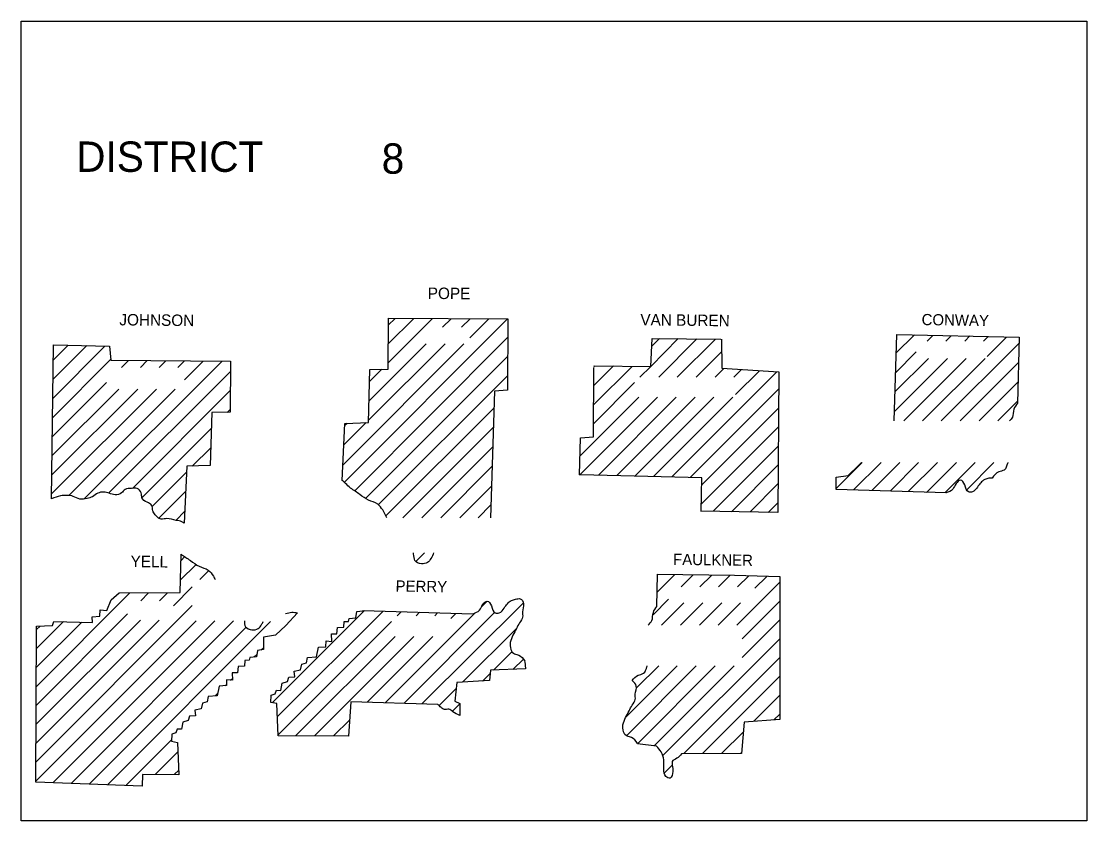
# Model space of a CAD drawing. Extents: x 23481 to 28196, y 1325020 to 1327623.
# Drawn here: x 27790.8 to 28190.8, y 1325699 to 1325999 of the extents above; entities that cross this region are included whole.
import ezdxf

# ---------------------------------------------------------------- set-up
doc = ezdxf.new("R2010")
doc.units = 0
doc.layers.add('S_ELECTRIC_UTILITIES_ANNOT', color=7, linetype='Continuous')

msp = doc.modelspace()

# ---------------------------------------------------------------- linework, layer by layer
at = {"layer": 'S_ELECTRIC_UTILITIES_ANNOT'}
msp.add_lwpolyline([(27790.76, 1325699.02), (27790.76, 1325999.02), (28190.76, 1325999.02), (28190.76, 1325699.02)], close=True, dxfattribs=at)
for points in [[(27911.26, 1325826.72), (27912.26, 1325848.12), (27921.06, 1325848.42), (27921.66, 1325868.32), (27928.56, 1325868.42), (27928.66, 1325887.62)], [(27912.06, 1325826.02), (27973.36, 1325887.32), (27973.36, 1325887.42)], [(27928.56, 1325870.82), (27945.16, 1325887.52)], [(27928.56, 1325877.92), (27938.16, 1325887.52)], [(27928.56, 1325885.02), (27931.16, 1325887.52)], [(27928.66, 1325887.62), (27973.46, 1325887.32)], [(27948.96, 1325884.22), (27952.16, 1325887.42)], [(27956.06, 1325884.22), (27959.26, 1325887.42)], [(27959.16, 1325880.22), (27966.26, 1325887.32)], [(27973.46, 1325887.32), (27973.26, 1325860.62), (27968.46, 1325860.22), (27966.96, 1325812.72)], [(27915.96, 1325822.82), (27973.36, 1325880.32)], [(28005.76, 1325869.72), (28027.06, 1325869.52), (28027.56, 1325880.02), (28053.36, 1325879.72)], [(28118.46, 1325849.02), (28119.46, 1325881.52)], [(28119.16, 1325874.42), (28126.06, 1325881.32)], [(28119.46, 1325881.52), (28165.36, 1325880.42), (28164.76, 1325855.72)], [(28130.86, 1325879.02), (28132.96, 1325881.12)], [(28137.86, 1325879.02), (28139.86, 1325881.02)], [(28144.96, 1325879.02), (28146.86, 1325880.92)], [(28152.06, 1325879.02), (28153.66, 1325880.62)], [(28153.36, 1325873.22), (28160.66, 1325880.52)], [(27802.16, 1325819.82), (27802.86, 1325877.62)], [(27802.56, 1325857.52), (27822.16, 1325877.12)], [(27802.66, 1325864.62), (27815.36, 1325877.32)], [(27802.76, 1325871.82), (27808.36, 1325877.42)], [(27802.86, 1325877.62), (27823.86, 1325877.12), (27824.36, 1325871.82)], [(27911.56, 1325832.62), (27956.96, 1325878.02)], [(27921.16, 1325849.32), (27949.86, 1325878.02)], [(27921.36, 1325856.62), (27942.76, 1325878.02)], [(28022.96, 1325865.42), (28027.06, 1325869.52), (28037.36, 1325879.92)], [(28027.36, 1325876.92), (28030.36, 1325879.92)], [(28030.06, 1325865.42), (28044.36, 1325879.82)], [(28037.06, 1325865.42), (28051.36, 1325879.72)], [(28053.66, 1325879.72), (28053.76, 1325868.82), (28075.16, 1325867.42), (28074.86, 1325814.72)], [(28136.16, 1325849.02), (28165.26, 1325878.12)], [(27802.56, 1325850.32), (27824.26, 1325872.12)], [(27920.16, 1325820.02), (27973.36, 1325873.22)], [(28044.16, 1325865.42), (28053.66, 1325874.92)], [(28118.56, 1325852.62), (28138.46, 1325872.52)], [(28118.76, 1325859.92), (28131.36, 1325872.52)], [(28118.96, 1325867.12), (28126.76, 1325874.92)], [(28122.06, 1325849.02), (28145.56, 1325872.52)], [(28129.16, 1325849.02), (28152.66, 1325872.52)], [(27814.36, 1325819.82), (27866.16, 1325871.52)], [(27824.36, 1325871.82), (27869.26, 1325871.52)], [(27828.36, 1325869.12), (27830.96, 1325871.72)], [(27835.46, 1325869.12), (27838.06, 1325871.72)], [(27842.56, 1325869.12), (27845.06, 1325871.62)], [(27849.56, 1325869.12), (27852.06, 1325871.62)], [(27869.26, 1325871.52), (27869.16, 1325852.32), (27862.26, 1325852.22), (27861.66, 1325832.32), (27852.86, 1325832.02), (27851.86, 1325810.62)], [(27852.06, 1325864.52), (27859.06, 1325871.52)], [(27921.46, 1325863.82), (27926.06, 1325868.42)], [(28000.36, 1325828.82), (28000.76, 1325842.72), (28005.56, 1325843.12), (28005.76, 1325869.12)], [(28005.66, 1325855.22), (28020.06, 1325869.52)], [(28005.76, 1325862.32), (28013.06, 1325869.72)], [(28005.76, 1325869.42), (28006.06, 1325869.72)], [(28051.26, 1325865.42), (28054.56, 1325868.72)], [(28058.26, 1325865.42), (28061.16, 1325868.32)], [(28143.26, 1325849.02), (28165.06, 1325870.82)], [(27823.66, 1325822.02), (27869.16, 1325867.52)], [(27924.86, 1325817.72), (27973.26, 1325866.02)], [(28035.06, 1325828.02), (28074.46, 1325867.42)], [(28058.86, 1325858.92), (28067.86, 1325867.82)], [(27802.26, 1325821.82), (27841.46, 1325861.02)], [(27802.36, 1325828.92), (27834.46, 1325861.02)], [(27802.36, 1325836.02), (27827.36, 1325861.02)], [(27802.46, 1325843.22), (27822.76, 1325863.52)], [(27808.56, 1325821.02), (27848.56, 1325861.02)], [(27832.46, 1325823.72), (27869.16, 1325860.42)], [(28005.66, 1325848.12), (28020.96, 1325863.42)], [(28041.96, 1325827.92), (28075.06, 1325861.02)], [(28150.36, 1325849.02), (28164.96, 1325863.62)], [(28000.46, 1325828.72), (28000.46, 1325828.82), (28029.56, 1325857.92)], [(28000.66, 1325836.02), (28022.56, 1325857.92)], [(28007.46, 1325828.72), (28036.66, 1325857.92)], [(28014.36, 1325828.52), (28043.76, 1325857.92)], [(28021.26, 1325828.42), (28050.76, 1325857.92)], [(28028.16, 1325828.22), (28057.96, 1325857.92)], [(28157.46, 1325849.02), (28164.76, 1325856.42)], [(27868.06, 1325852.22), (27869.16, 1325853.32)], [(27927.56, 1325813.32), (27968.26, 1325853.92)], [(28046.26, 1325825.12), (28075.06, 1325853.82)], [(27911.86, 1325840.02), (27920.26, 1325848.42)], [(27912.26, 1325847.42), (27913.06, 1325848.22)], [(27836.16, 1325820.32), (27862.06, 1325846.22)], [(27934.06, 1325812.72), (27968.06, 1325846.72)], [(28046.06, 1325817.82), (28075.06, 1325846.82)], [(27854.96, 1325832.02), (27861.86, 1325838.92)], [(27941.16, 1325812.72), (27967.76, 1325839.32)], [(28050.46, 1325815.12), (28074.96, 1325839.62)], [(27948.26, 1325812.72), (27967.56, 1325832.02)], [(28057.36, 1325814.92), (28074.96, 1325832.62)], [(28096.66, 1325823.32), (28096.66, 1325827.92), (28101.16, 1325828.62), (28105.06, 1325832.32), (28106.16, 1325833.42)], [(28096.66, 1325823.72), (28106.46, 1325833.42)], [(28103.26, 1325823.22), (28113.56, 1325833.42)], [(28110.06, 1325822.92), (28120.56, 1325833.42)], [(28116.96, 1325822.72), (28127.66, 1325833.42)], [(28123.76, 1325822.52), (28134.76, 1325833.42)], [(28130.66, 1325822.22), (28141.86, 1325833.42)], [(28137.46, 1325822.02), (28148.86, 1325833.42)], [(28145.76, 1325823.22), (28155.96, 1325833.42)], [(27839.96, 1325817.02), (27852.66, 1325829.72)], [(28045.96, 1325815.12), (28046.26, 1325827.72), (28000.56, 1325828.82)], [(27955.36, 1325812.72), (27967.36, 1325824.72)], [(28064.36, 1325814.92), (28074.86, 1325825.42)], [(27842.56, 1325812.62), (27852.46, 1325822.52)], [(28137.96, 1325822.02), (28096.76, 1325823.32)], [(27962.26, 1325812.72), (27967.06, 1325817.52)], [(28071.16, 1325814.72), (28074.86, 1325818.32)], [(27848.86, 1325811.82), (27852.06, 1325815.02)], [(28074.86, 1325814.72), (28045.76, 1325815.12)], [(27796.26, 1325713.52), (27796.46, 1325772.02), (27802.46, 1325772.22), (27802.96, 1325773.82), (27817.46, 1325773.42), (27817.36, 1325775.52), (27820.26, 1325775.82), (27820.36, 1325778.12), (27822.86, 1325777.92), (27824.56, 1325781.92), (27827.56, 1325784.52), (27850.36, 1325784.62), (27850.76, 1325799.02)], [(27850.76, 1325796.72), (27852.06, 1325798.02)], [(27938.86, 1325796.32), (27942.16, 1325799.52)], [(27850.46, 1325789.32), (27856.36, 1325795.22)], [(27857.76, 1325789.52), (27861.06, 1325792.82)], [(28029.36, 1325779.42), (28029.66, 1325791.52)], [(28029.46, 1325791.52), (28058.56, 1325791.12)], [(28029.46, 1325784.82), (28035.96, 1325791.32)], [(28038.46, 1325786.72), (28042.96, 1325791.32)], [(28058.56, 1325791.12), (28075.56, 1325790.62), (28075.56, 1325737.02), (28062.16, 1325736.02), (28061.16, 1325724.22), (28038.66, 1325724.12)], [(28045.46, 1325786.72), (28049.96, 1325791.22)], [(28052.56, 1325786.72), (28056.96, 1325791.12)], [(28059.46, 1325772.42), (28075.56, 1325788.52)], [(28059.66, 1325786.72), (28063.86, 1325790.92)], [(28066.16, 1325786.22), (28070.66, 1325790.72)], [(27796.46, 1325749.42), (27831.46, 1325784.52)], [(27835.66, 1325781.52), (27838.56, 1325784.52)], [(27842.66, 1325781.52), (27845.66, 1325784.52)], [(27847.86, 1325779.62), (27854.96, 1325786.72)], [(27941.16, 1325742.82), (27979.26, 1325780.82)], [(27963.56, 1325779.32), (27965.66, 1325781.42)], [(28027.96, 1325776.22), (28033.76, 1325782.12)], [(28031.16, 1325772.42), (28039.56, 1325780.82)], [(28038.26, 1325772.42), (28046.66, 1325780.82)], [(28045.36, 1325772.42), (28053.76, 1325780.82)], [(28052.36, 1325772.42), (28060.76, 1325780.82)], [(28061.36, 1325767.22), (28075.56, 1325781.42)], [(27796.36, 1325721.12), (27854.96, 1325779.72)], [(27796.46, 1325742.32), (27830.66, 1325776.62)], [(27894.46, 1325777.02), (27890.06, 1325772.32), (27886.16, 1325768.62), (27881.66, 1325767.92), (27881.66, 1325763.22), (27879.46, 1325762.92), (27879.06, 1325760.52), (27876.56, 1325760.32), (27876.36, 1325759.22), (27874.66, 1325759.12), (27874.56, 1325757.02), (27872.16, 1325756.92), (27871.96, 1325754.52), (27869.96, 1325754.52), (27870.06, 1325751.72), (27867.86, 1325751.92), (27867.76, 1325749.72), (27865.06, 1325749.52), (27864.26, 1325745.92), (27860.86, 1325745.62), (27860.56, 1325743.62), (27858.76, 1325743.12), (27858.26, 1325741.02), (27855.96, 1325740.52), (27856.16, 1325738.42), (27853.86, 1325738.22), (27853.46, 1325736.62), (27851.36, 1325736.02), (27850.86, 1325733.32), (27849.26, 1325733.42), (27848.76, 1325732.02), (27847.26, 1325731.52), (27847.16, 1325728.82), (27849.46, 1325728.42), (27849.86, 1325716.22)], [(27887.16, 1325730.82), (27886.76, 1325743.02), (27884.46, 1325743.42), (27884.56, 1325746.12), (27886.06, 1325746.62), (27886.56, 1325748.02), (27888.16, 1325747.92), (27888.66, 1325750.62), (27890.76, 1325751.22), (27891.16, 1325752.82), (27893.46, 1325753.02), (27893.26, 1325755.12), (27895.56, 1325755.62), (27896.06, 1325757.72), (27897.86, 1325758.22), (27898.16, 1325760.22), (27901.56, 1325760.52), (27902.36, 1325764.12), (27905.06, 1325764.32), (27905.16, 1325766.52), (27907.36, 1325766.32), (27907.26, 1325769.12), (27909.26, 1325769.12), (27909.46, 1325771.52), (27911.86, 1325771.62), (27911.96, 1325773.72), (27913.66, 1325773.82), (27913.86, 1325774.92), (27916.36, 1325775.12), (27916.76, 1325777.52), (27918.96, 1325777.82), (27918.96, 1325777.92)], [(27885.06, 1325743.32), (27919.66, 1325777.92)], [(27886.96, 1325738.12), (27926.56, 1325777.62)], [(27919.06, 1325777.92), (27960.26, 1325776.62)], [(27927.56, 1325743.32), (27960.96, 1325776.72)], [(27931.86, 1325775.92), (27933.36, 1325777.42)], [(27934.36, 1325743.02), (27968.46, 1325777.12)], [(27938.96, 1325775.92), (27940.26, 1325777.22)], [(27945.96, 1325775.92), (27947.06, 1325777.02)], [(27952.06, 1325774.92), (27953.86, 1325776.72)], [(27796.36, 1325728.12), (27842.56, 1325774.32)], [(27796.36, 1325714.02), (27856.36, 1325774.02)], [(27796.46, 1325735.32), (27835.46, 1325774.32)], [(27796.46, 1325763.62), (27806.66, 1325773.72)], [(27796.46, 1325756.62), (27813.46, 1325773.52)], [(27796.46, 1325770.72), (27797.86, 1325772.02)], [(27802.76, 1325713.32), (27863.46, 1325774.02)], [(27809.46, 1325713.02), (27870.46, 1325774.02)], [(27823.16, 1325712.52), (27884.36, 1325773.72)], [(27887.16, 1325731.22), (27929.76, 1325773.82)], [(28061.36, 1325760.22), (28075.56, 1325774.42)], [(27816.26, 1325712.72), (27875.16, 1325771.62)], [(27893.76, 1325730.82), (27931.16, 1325768.12)], [(27900.86, 1325730.82), (27938.16, 1325768.12)], [(27920.66, 1325743.52), (27945.26, 1325768.12)], [(27956.46, 1325751.02), (27976.76, 1325771.32)], [(27880.76, 1325763.12), (27881.66, 1325763.92), (27881.86, 1325764.12)], [(28031.56, 1325723.32), (28075.56, 1325767.32)], [(27878.06, 1325760.42), (27879.26, 1325761.52)], [(27968.06, 1325755.52), (27974.96, 1325762.42)], [(28039.56, 1325724.22), (28075.56, 1325760.22)], [(27979.76, 1325758.72), (27980.06, 1325756.02), (27966.96, 1325755.52), (27966.56, 1325751.62), (27954.26, 1325750.92), (27953.56, 1325743.92), (27955.36, 1325743.02), (27955.36, 1325738.52)], [(27975.36, 1325755.72), (27979.26, 1325759.62)], [(28017.66, 1325737.72), (28037.06, 1325757.12)], [(28018.06, 1325731.02), (28044.16, 1325757.12)], [(28021.86, 1325749.02), (28030.06, 1325757.12)], [(28022.06, 1325727.92), (28051.26, 1325757.12)], [(28028.46, 1325727.22), (28058.36, 1325757.12)], [(27869.36, 1325751.72), (27870.06, 1325752.32)], [(27963.96, 1325751.42), (27966.76, 1325754.22)], [(28046.56, 1325724.22), (28075.56, 1325753.22)], [(27867.36, 1325749.62), (27867.66, 1325750.02)], [(27947.56, 1325742.12), (27954.06, 1325748.62)], [(27863.56, 1325745.82), (27864.46, 1325746.72)], [(28065.76, 1325736.32), (28075.56, 1325746.12)], [(27947.16, 1325742.62), (27914.46, 1325743.62), (27913.56, 1325730.72), (27887.16, 1325730.82)], [(27952.56, 1325740.02), (27955.36, 1325742.92)], [(27907.96, 1325730.82), (27914.06, 1325736.82)], [(28073.36, 1325736.82), (28075.56, 1325739.02)], [(28053.66, 1325724.22), (28061.86, 1325732.42)], [(27829.96, 1325712.22), (27847.26, 1325729.52)], [(27841.06, 1325716.32), (27849.56, 1325724.82)], [(28029.26, 1325727.02), (28022.06, 1325727.82)], [(28060.76, 1325724.22), (28061.26, 1325724.72)], [(27849.86, 1325716.22), (27836.26, 1325716.32), (27836.16, 1325712.02)], [(27848.16, 1325716.32), (27849.86, 1325718.02)], [(28032.26, 1325717.02), (28035.16, 1325719.82)], [(27836.16, 1325712.02), (27796.26, 1325713.52)]]:
    msp.add_lwpolyline(points, dxfattribs=at)
for points in [[(28164.76, 1325855.72), (28163.46, 1325853.42), (28162.86, 1325850.42), (28161.76, 1325849.02)], [(28161.16, 1325833.42), (28161.06, 1325833.12), (28159.76, 1325830.62), (28157.76, 1325829.92), (28155.26, 1325827.62)], [(27914.36, 1325823.82), (27912.46, 1325825.62), (27911.26, 1325826.72)], [(28155.26, 1325827.62), (28154.06, 1325827.52), (28152.46, 1325827.02), (28150.96, 1325825.82), (28149.76, 1325824.22), (28147.86, 1325822.42), (28146.36, 1325822.42), (28144.96, 1325825.02), (28143.36, 1325826.82), (28141.76, 1325825.52), (28140.46, 1325823.42), (28137.96, 1325822.02)], [(27851.86, 1325810.62), (27851.06, 1325811.22), (27848.86, 1325811.72), (27845.46, 1325812.42), (27843.26, 1325812.22), (27841.96, 1325812.82), (27841.06, 1325813.82), (27840.16, 1325815.32), (27839.66, 1325817.42), (27837.96, 1325818.52), (27836.06, 1325820.22), (27835.76, 1325822.02), (27834.26, 1325823.72), (27832.16, 1325823.72), (27829.76, 1325823.32), (27828.36, 1325822.02), (27825.96, 1325821.32), (27823.76, 1325821.92), (27821.66, 1325822.32), (27819.46, 1325821.92), (27817.46, 1325820.62), (27815.46, 1325819.92), (27812.76, 1325819.72), (27810.26, 1325820.72), (27807.86, 1325821.12), (27805.46, 1325820.92), (27802.16, 1325819.82)], [(27927.96, 1325812.72), (27926.46, 1325815.62), (27924.56, 1325817.82), (27921.16, 1325819.32), (27917.86, 1325821.42), (27914.36, 1325823.82)], [(27850.76, 1325799.02), (27854.26, 1325796.62), (27857.56, 1325794.52), (27860.96, 1325793.02), (27862.86, 1325790.82), (27863.56, 1325789.52)], [(27945.56, 1325799.52), (27944.56, 1325797.42), (27943.26, 1325795.92), (27940.96, 1325795.42), (27938.56, 1325796.62), (27938.06, 1325799.12), (27937.96, 1325799.52)], [(27960.26, 1325776.62), (27962.76, 1325778.02), (27964.06, 1325780.12), (27965.66, 1325781.42), (27967.26, 1325779.62), (27968.66, 1325777.02), (27970.16, 1325777.02), (27972.06, 1325778.82), (27973.26, 1325780.42), (27974.76, 1325781.62), (27976.36, 1325782.12), (27978.06, 1325782.32), (27979.36, 1325780.42), (27978.96, 1325777.42), (27978.96, 1325775.42), (27977.86, 1325773.32), (27976.66, 1325771.12), (27975.36, 1325768.62), (27974.36, 1325765.92), (27974.56, 1325763.32), (27975.96, 1325761.62), (27977.56, 1325761.12), (27979.76, 1325758.92)], [(27889.96, 1325776.72), (27892.36, 1325777.22), (27894.46, 1325777.02)], [(28026.06, 1325772.42), (28027.46, 1325774.12), (28028.06, 1325777.12), (28029.36, 1325779.42)], [(27874.56, 1325774.02), (27874.96, 1325771.82), (27877.36, 1325770.62), (27879.66, 1325771.12), (27880.96, 1325772.62), (27881.56, 1325773.72)], [(28020.16, 1325751.62), (28022.36, 1325753.62), (28024.36, 1325754.32), (28025.66, 1325756.82), (28025.76, 1325757.12)], [(28022.06, 1325728.02), (28019.86, 1325730.22), (28018.26, 1325730.72), (28016.86, 1325732.42), (28016.66, 1325735.02), (28017.66, 1325737.72), (28018.96, 1325740.22), (28020.16, 1325742.42), (28021.26, 1325744.52), (28021.26, 1325746.52), (28021.66, 1325749.52), (28020.16, 1325751.62)], [(27955.36, 1325738.52), (27952.76, 1325739.92), (27951.26, 1325740.82), (27949.66, 1325740.72), (27948.36, 1325741.52), (27947.16, 1325742.62)], [(28038.66, 1325724.12), (28036.86, 1325722.42), (28035.16, 1325721.22), (28035.16, 1325719.82), (28035.36, 1325717.42), (28034.36, 1325715.02), (28032.76, 1325715.62), (28031.96, 1325718.42), (28031.96, 1325721.82), (28030.96, 1325724.82), (28029.26, 1325727.02)]]:
    msp.add_spline(points, degree=3, dxfattribs=at)

# ---------------------------------------------------------------- texts
for s, p in [('DISTRICT', (27811.36, 1325942.52)), ('8', (27926.06, 1325941.82))]:
    msp.add_text(s, height=11.4, dxfattribs=at).set_placement(p)
for s, height, rotation, p in [('POPE', 4.301, 359.6155, (27943.36, 1325894.82)), ('JOHNSON', 4.301, 359.3514, (27827.56, 1325884.92)), ('VAN BUREN', 4.301, 359.3508, (28023.16, 1325884.92)), ('CONWAY', 4.199, 359.0371, (28128.76, 1325885.02)), ('YELL', 4.301, 359.1987, (27831.76, 1325794.22)), ('FAULKNER', 4.201, 359.2486, (28035.46, 1325795.02)), ('PERRY', 4.201, 359.0858, (27931.26, 1325785.02))]:
    msp.add_text(s, height=height, rotation=rotation, dxfattribs=at).set_placement(p)

doc.saveas('drawing.dxf')
